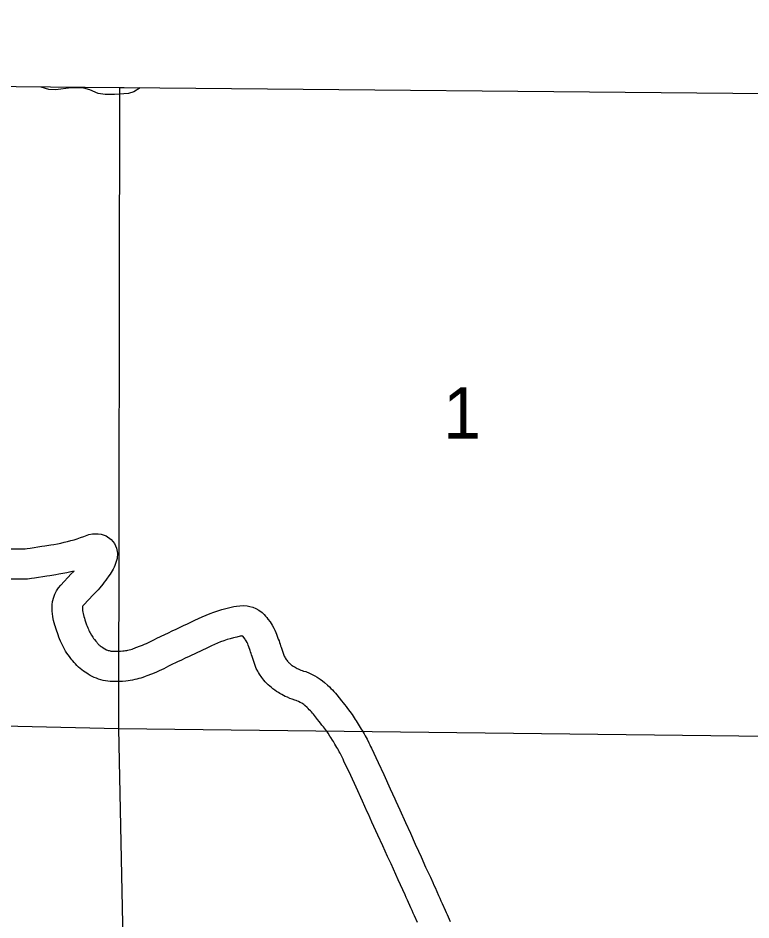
# Model space of a CAD drawing. Extents: x -19 to 366, y -4 to 359.
# Drawn here: x 138.218 to 139.362, y 202.778 to 204.187 of the extents above; entities that cross this region are included whole.
import ezdxf

# ---------------------------------------------------------------- set-up
doc = ezdxf.new("R2010")
doc.units = 0
for name, color, linetype in [('Level 10', 7, 'Continuous'), ('Level 2', 7, 'Continuous'), ('Level 35', 7, 'Continuous'), ('Level 5', 7, 'Continuous'), ('Level 60', 7, 'Continuous')]:
    doc.layers.add(name, color=color, linetype=linetype)

msp = doc.modelspace()

# ---------------------------------------------------------------- linework, layer by layer
at = {"layer": 'Level 10'}
for p, q in [((138.2759, 203.235), (138.2758, 203.2354)), ((138.5816, 203.194), (138.5816, 203.1939))]:
    msp.add_line(p, q, dxfattribs=at)
for points in [[(138.207, 203.3572), (138.2222, 203.3573), (138.2248, 203.3574), (138.2274, 203.3574), (138.2285, 203.3574), (138.2318, 203.3579), (138.2363, 203.3585), (138.2549, 203.3614), (138.2594, 203.3621), (138.2687, 203.3636), (138.2733, 203.3644), (138.2789, 203.3654), (138.2841, 203.3664), (138.2893, 203.3676), (138.2946, 203.3688), (138.2998, 203.3702), (138.305, 203.3717), (138.31, 203.3733), (138.3153, 203.3751), (138.3203, 203.3769), (138.3279, 203.38), (138.3336, 203.3809), (138.3378, 203.3811), (138.3425, 203.381), (138.3474, 203.3802), (138.3552, 203.3779), (138.363, 203.3719), (138.368, 203.3655), (138.3712, 203.3582), (138.3727, 203.3504), (138.3723, 203.3425), (138.3709, 203.3375), (138.3699, 203.3344), (138.3687, 203.3314), (138.3677, 203.3289), (138.3662, 203.3258), (138.3646, 203.3229), (138.3631, 203.3203), (138.3614, 203.3178), (138.3594, 203.3151), (138.3582, 203.3136), (138.3567, 203.3114), (138.3544, 203.3083), (138.3521, 203.3053), (138.3497, 203.3022), (138.345, 203.2965), (138.3425, 203.2936), (138.3399, 203.2907), (138.3349, 203.2855), (138.32, 203.2698), (138.3194, 203.2691), (138.3189, 203.2683), (138.3184, 203.2673), (138.3181, 203.2664), (138.3181, 203.2664), (138.3181, 203.2652), (138.3182, 203.2621), (138.3183, 203.261), (138.3186, 203.2583), (138.319, 203.2562), (138.3203, 203.2517), (138.3211, 203.2489)], [(138.2758, 203.2354), (138.2749, 203.2383), (138.2729, 203.2452), (138.2718, 203.2511), (138.2711, 203.2565), (138.2709, 203.2594), (138.2707, 203.2642), (138.2707, 203.2671), (138.2708, 203.2699), (138.2711, 203.2752), (138.2733, 203.2819), (138.2752, 203.2867), (138.2777, 203.2916), (138.2807, 203.2964), (138.2841, 203.3008), (138.3006, 203.3181), (138.3049, 203.3226), (138.3001, 203.3214), (138.2938, 203.32), (138.2873, 203.3188), (138.2812, 203.3177), (138.2765, 203.3169), (138.2671, 203.3154), (138.2623, 203.3146), (138.2434, 203.3117), (138.2386, 203.311), (138.2325, 203.3102), (138.2283, 203.31), (138.2257, 203.31), (138.223, 203.3099), (138.2067, 203.3098)], [(138.3211, 203.2489), (138.3219, 203.2467), (138.3246, 203.2388), (138.3255, 203.2364), (138.3265, 203.2339), (138.3273, 203.2317), (138.3281, 203.23), (138.3291, 203.2279), (138.33, 203.2262), (138.3321, 203.2225), (138.3331, 203.2209), (138.3344, 203.2192), (138.3356, 203.2175), (138.3369, 203.2158), (138.3388, 203.2134), (138.3403, 203.2115), (138.3412, 203.2103), (138.3421, 203.2093), (138.3429, 203.2085), (138.3438, 203.2076), (138.3447, 203.2069), (138.3459, 203.2059), (138.3472, 203.2049), (138.3482, 203.2043), (138.3499, 203.2032), (138.3521, 203.2018), (138.3531, 203.2012), (138.3558, 203.1998), (138.357, 203.1993), (138.3585, 203.1988), (138.3599, 203.1984), (138.3612, 203.198), (138.3626, 203.1977), (138.3637, 203.1975), (138.3646, 203.1975), (138.3662, 203.1974), (138.3701, 203.1973), (138.3717, 203.1973), (138.3756, 203.1974), (138.3773, 203.1975), (138.3811, 203.1978), (138.3831, 203.1981), (138.3853, 203.1984), (138.3873, 203.1987), (138.3891, 203.1991), (138.3913, 203.1996), (138.3934, 203.2002), (138.3956, 203.2008), (138.3977, 203.2015), (138.3995, 203.2021), (138.4016, 203.203), (138.4086, 203.2057), (138.4117, 203.2069), (138.4149, 203.2083), (138.418, 203.2097), (138.4244, 203.2127), (138.4275, 203.2142), (138.4304, 203.2158), (138.4342, 203.2178), (138.4467, 203.2236), (138.4526, 203.2264), (138.4584, 203.2292), (138.4644, 203.2319), (138.4761, 203.2376), (138.4819, 203.2404), (138.4937, 203.246), (138.4992, 203.2487), (138.5051, 203.2514), (138.5112, 203.254), (138.5173, 203.2563), (138.5234, 203.2585), (138.5296, 203.2606), (138.5357, 203.2624), (138.542, 203.2642), (138.5484, 203.2658), (138.5546, 203.2672), (138.5589, 203.268), (138.5641, 203.2686), (138.5696, 203.2687), (138.5752, 203.2681), (138.5796, 203.2673), (138.5841, 203.2663), (138.5891, 203.2642), (138.5938, 203.2617), (138.5986, 203.2581), (138.6021, 203.2546), (138.6041, 203.2522), (138.606, 203.25), (138.6078, 203.2476), (138.611, 203.2432), (138.6127, 203.2406), (138.6142, 203.2382), (138.617, 203.2335), (138.6187, 203.2301), (138.6201, 203.2268), (138.6212, 203.2241), (138.624, 203.2164), (138.6251, 203.2135), (138.6259, 203.2108), (138.6267, 203.2084)], [(138.5816, 203.1939), (138.5808, 203.1964), (138.5801, 203.1985), (138.5795, 203.2003), (138.577, 203.2069), (138.5762, 203.2089), (138.5757, 203.2102), (138.5754, 203.2109), (138.5736, 203.2138), (138.5727, 203.2153), (138.572, 203.2164), (138.57, 203.2191), (138.5691, 203.2203), (138.5683, 203.2212), (138.5682, 203.2212), (138.5676, 203.2213), (138.567, 203.2213), (138.5662, 203.2212), (138.5644, 203.2209), (138.5591, 203.2196), (138.5541, 203.2184), (138.549, 203.217), (138.5439, 203.2155), (138.5389, 203.2138), (138.5339, 203.212), (138.529, 203.2101), (138.5242, 203.208), (138.5194, 203.2058), (138.5143, 203.2034), (138.5025, 203.1977), (138.4966, 203.1949), (138.4846, 203.1892), (138.4787, 203.1864), (138.4728, 203.1835), (138.4667, 203.1807), (138.4555, 203.1755), (138.4526, 203.1739), (138.4488, 203.172), (138.445, 203.1701), (138.4378, 203.1667), (138.4339, 203.1649), (138.43, 203.1633), (138.4261, 203.1617), (138.4189, 203.1589), (138.416, 203.1577), (138.4125, 203.1565), (138.4093, 203.1555), (138.4061, 203.1546), (138.403, 203.1537), (138.3997, 203.153), (138.3962, 203.1522), (138.3927, 203.1516), (138.3894, 203.1511), (138.3859, 203.1507), (138.3807, 203.1503), (138.3777, 203.1501), (138.3725, 203.1499), (138.3695, 203.1499), (138.3644, 203.1501), (138.3614, 203.1502), (138.3577, 203.1505), (138.3539, 203.1512), (138.3503, 203.1519), (138.3467, 203.1529), (138.3432, 203.1539), (138.34, 203.1552), (138.3364, 203.1566), (138.3301, 203.1597), (138.3268, 203.1618), (138.3248, 203.1631), (138.3225, 203.1645), (138.3196, 203.1665), (138.3172, 203.1683), (138.3146, 203.1703), (138.312, 203.1726), (138.3095, 203.1749), (138.307, 203.1775), (138.3049, 203.1799), (138.3029, 203.1824), (138.3015, 203.1842), (138.2999, 203.1862), (138.2978, 203.189), (138.2958, 203.1917), (138.2938, 203.1945), (138.2918, 203.1977), (138.2883, 203.2037), (138.2867, 203.2069), (138.2853, 203.2098), (138.2837, 203.2132), (138.2824, 203.2166), (138.2812, 203.2196), (138.28, 203.2229), (138.2769, 203.2318), (138.2759, 203.235)], [(138.6267, 203.2084), (138.6275, 203.2057), (138.6282, 203.2036), (138.633, 203.1897), (138.6331, 203.1897), (138.634, 203.1881), (138.6347, 203.1869), (138.6364, 203.1844), (138.6372, 203.1834), (138.6383, 203.1819), (138.6392, 203.1808), (138.6401, 203.1799), (138.6409, 203.1791), (138.6419, 203.1782), (138.6432, 203.1771), (138.6446, 203.1759), (138.6457, 203.1751), (138.6471, 203.1742), (138.649, 203.173), (138.6501, 203.1723), (138.6517, 203.1715), (138.6533, 203.1706), (138.655, 203.1698), (138.6573, 203.1687), (138.6592, 203.1679), (138.6613, 203.1672), (138.6632, 203.1665), (138.6671, 203.1655), (138.6725, 203.1632), (138.6767, 203.1612), (138.681, 203.159), (138.6849, 203.1567), (138.6896, 203.1538), (138.6931, 203.1511), (138.6959, 203.1488), (138.701, 203.1443), (138.7037, 203.1418), (138.7061, 203.1393), (138.7084, 203.137), (138.7108, 203.1344), (138.7131, 203.1318), (138.7154, 203.1291), (138.7227, 203.1199), (138.725, 203.117), (138.7274, 203.114), (138.7297, 203.1109), (138.7319, 203.108), (138.7391, 203.0985), (138.741, 203.0957), (138.7441, 203.091), (138.7458, 203.0885), (138.7489, 203.0835), (138.7504, 203.0811), (138.752, 203.0784), (138.7535, 203.0758), (138.7548, 203.0736), (138.7563, 203.0711), (138.7579, 203.0684), (138.7595, 203.0654), (138.7611, 203.0625), (138.7625, 203.0598), (138.7654, 203.0542), (138.7668, 203.0512), (138.7682, 203.0483), (138.7693, 203.0458), (138.7801, 203.0235), (138.7889, 203.0048), (138.7989, 202.9824), (138.8058, 202.9667), (138.8077, 202.9632), (138.8135, 202.9495), (138.8225, 202.9299), (138.8303, 202.9131), (138.8377, 202.8962), (138.8431, 202.8849), (138.847, 202.8759), (138.8541, 202.8599), (138.8614, 202.8443), (138.8652, 202.836), (138.8669, 202.832), (138.8688, 202.828), (138.8743, 202.8157), (138.8762, 202.8116), (138.878, 202.8076), (138.8798, 202.8034), (138.8845, 202.7928), (138.8861, 202.7893), (138.8877, 202.7858), (138.8892, 202.7824), (138.8925, 202.7753)], [(138.8413, 202.7735), (138.8366, 202.7842), (138.8348, 202.7881), (138.833, 202.7922), (138.8311, 202.7964), (138.8257, 202.8083), (138.8238, 202.8125), (138.8219, 202.8167), (138.8184, 202.8246), (138.8111, 202.8403), (138.8037, 202.8569), (138.8, 202.8654), (138.7947, 202.8765), (138.7872, 202.8935), (138.7795, 202.91), (138.7702, 202.9303), (138.7648, 202.9429), (138.763, 202.9463), (138.7557, 202.9632), (138.7458, 202.9851), (138.7374, 203.0031), (138.7264, 203.0257), (138.7251, 203.0286), (138.724, 203.0309), (138.723, 203.0331), (138.7205, 203.038), (138.7192, 203.0404), (138.7179, 203.0427), (138.7168, 203.0449), (138.7154, 203.0471), (138.714, 203.0497), (138.7125, 203.0522), (138.7113, 203.0543), (138.71, 203.0563), (138.7087, 203.0585), (138.706, 203.0627), (138.7046, 203.0648), (138.7017, 203.0693), (138.7006, 203.0709), (138.6943, 203.0792), (138.6921, 203.0821), (138.6899, 203.085), (138.6877, 203.0878), (138.6854, 203.0908), (138.6789, 203.099), (138.6774, 203.1007), (138.6757, 203.1026), (138.6741, 203.1043), (138.6724, 203.1061), (138.6706, 203.1078), (138.6691, 203.1093), (138.6653, 203.1127), (138.6636, 203.114), (138.6624, 203.115), (138.6606, 203.1161), (138.6582, 203.1175), (138.6557, 203.1188), (138.6531, 203.12), (138.6516, 203.1206), (138.6496, 203.1212), (138.6456, 203.1225), (138.6419, 203.1238), (138.6382, 203.1254), (138.6349, 203.1269), (138.6321, 203.1283), (138.6294, 203.1297), (138.6266, 203.1312), (138.6242, 203.1327), (138.6212, 203.1346), (138.6185, 203.1364), (138.6156, 203.1385), (138.6131, 203.1406), (138.6107, 203.1426), (138.608, 203.145), (138.6057, 203.1474), (138.6035, 203.1498), (138.6016, 203.1521), (138.5999, 203.1541), (138.598, 203.1566), (138.5946, 203.1616), (138.5931, 203.1643), (138.5918, 203.1665), (138.5896, 203.1705), (138.5831, 203.1891), (138.5823, 203.1919), (138.5816, 203.194)]]:
    msp.add_lwpolyline(points, dxfattribs=at)
at = {"layer": 'Level 2'}
msp.add_lwpolyline([(139.3896, 204.0685), (138.383, 204.0778), (138.3761, 204.0776), (137.7294, 204.084)], dxfattribs=at)
at = {"layer": 'Level 35'}
msp.add_lwpolyline([(138.4084, 204.0775), (138.3982, 204.0714), (138.3902, 204.0691), (138.3683, 204.0672), (138.3536, 204.0672), (138.3426, 204.0691), (138.3297, 204.0744), (138.3203, 204.077), (138.3006, 204.0778), (138.2761, 204.0747), (138.2655, 204.0751), (138.2538, 204.0788)], dxfattribs=at)
at = {"layer": 'Level 5'}
for points in [[(138.3761, 204.0776), (138.3744, 203.0767)], [(137.3855, 203.0998), (138.3744, 203.0767)], [(138.3744, 203.0767), (139.3874, 203.0648)], [(138.3744, 203.0767), (138.3811, 202.7458)]]:
    msp.add_lwpolyline(points, dxfattribs=at)
at = {"layer": 'Level 60'}
for points in [[(146.7783, 1.697), (146.5788, 10.3131), (146.3785, 18.9294), (146.1776, 27.5458), (145.9759, 36.1624), (145.7736, 44.7791), (145.5705, 53.396), (145.3668, 62.013), (145.1624, 70.6301), (144.9572, 79.2474), (144.7514, 87.8648), (144.5449, 96.4823), (144.3377, 105.1), (144.1299, 113.7179), (143.9213, 122.3359), (143.712, 130.954), (143.5021, 139.5723), (143.2915, 148.1907), (143.0802, 156.8092), (142.8682, 165.4279), (142.6555, 174.0468), (142.4422, 182.6658), (142.2282, 191.2849), (142.0135, 199.9042), (141.7981, 208.5236), (141.582, 217.1432), (141.3653, 225.7629), (141.1479, 234.3828), (140.9298, 243.0028), (140.711, 251.623), (140.4916, 260.2433), (140.2715, 268.8638), (140.0508, 277.4844), (139.8293, 286.1051), (139.6072, 294.726), (139.3845, 303.3471), (139.161, 311.9683), (138.937, 320.5896), (138.7122, 329.2111), (138.4868, 337.8328), (138.2607, 346.4546)], [(139.4406, 1.5315), (139.2511, 10.1473), (139.0608, 18.7633), (138.8699, 27.3793), (138.6784, 35.9956), (138.4861, 44.6119), (138.2932, 53.2285), (138.0997, 61.8451), (137.9055, 70.4619), (137.7106, 79.0789), (137.5151, 87.6959), (137.319, 96.3132), (137.1221, 104.9306), (136.9247, 113.5481), (136.7265, 122.1658), (136.5278, 130.7836), (136.3283, 139.4016), (136.1282, 148.0197), (135.9275, 156.6379), (135.7261, 165.2564), (135.5241, 173.8749), (135.3214, 182.4936), (135.1181, 191.1125), (134.9141, 199.7315), (134.7095, 208.3506), (134.5043, 216.9699), (134.2984, 225.5894), (134.0919, 234.209), (133.8847, 242.8288), (133.6769, 251.4487), (133.4685, 260.0687), (133.2594, 268.6889), (133.0497, 277.3093), (132.8393, 285.9298), (132.6283, 294.5504), (132.4167, 303.1713), (132.2044, 311.7922), (131.9916, 320.4133), (131.778, 329.0346), (131.5639, 337.656), (131.3491, 346.2776)], [(0, 198.1326), (7.1014, 198.137), (14.2028, 198.1503), (21.3042, 198.1724), (28.4055, 198.2034), (35.5068, 198.2433), (42.6081, 198.292), (49.7092, 198.3496), (56.8103, 198.4161), (63.9113, 198.4913), (71.0123, 198.5755), (78.1131, 198.6685), (85.2137, 198.7704), (92.3143, 198.8811), (99.4147, 199.0007), (106.5149, 199.1291), (113.615, 199.2664), (120.7149, 199.4126), (127.8146, 199.5676), (134.9141, 199.7315), (142.0135, 199.9042), (149.1125, 200.0858), (156.2114, 200.2762), (163.31, 200.4755), (170.4084, 200.6837), (177.5065, 200.9007), (184.6043, 201.1265), (191.7018, 201.3612), (198.799, 201.6048), (205.896, 201.8572), (212.9926, 202.1185), (220.0888, 202.3886), (227.1848, 202.6676), (234.2803, 202.9554), (241.3755, 203.2521), (248.4704, 203.5576), (255.5648, 203.872), (262.6589, 204.1952), (269.7525, 204.5273), (276.8457, 204.8682), (283.9385, 205.218), (291.0309, 205.5766), (298.1228, 205.9441), (305.2142, 206.3204), (312.3051, 206.7056), (319.3956, 207.0996), (326.4856, 207.5024), (333.5751, 207.9141), (340.664, 208.3347)]]:
    msp.add_spline(points, degree=3, dxfattribs=at)

# ---------------------------------------------------------------- texts
at = {"layer": 'Level 5'}
msp.add_text('1', height=0.08, dxfattribs=at).set_placement((138.8811, 203.5298))

doc.saveas('drawing.dxf')
